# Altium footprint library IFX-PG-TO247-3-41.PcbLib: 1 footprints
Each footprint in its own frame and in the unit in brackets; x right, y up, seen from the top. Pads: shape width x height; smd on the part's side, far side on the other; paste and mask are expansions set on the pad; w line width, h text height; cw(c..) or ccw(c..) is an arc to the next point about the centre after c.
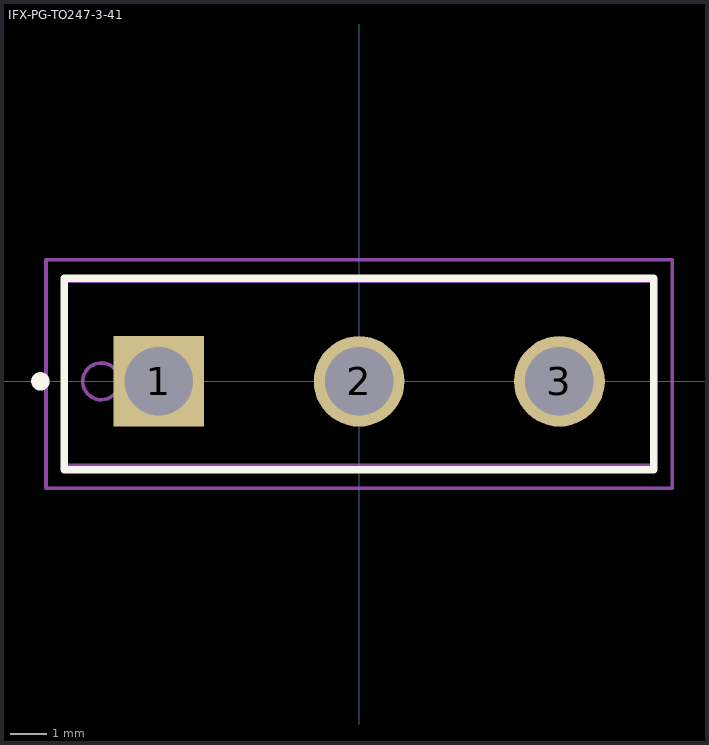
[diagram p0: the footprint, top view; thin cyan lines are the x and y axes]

## IFX-PG-TO247-3-41 [mm] "TO247-Diode; 3 pin, 5.44 mm pitch, 15.90 mm L X 5.00 mm W X 26.00 mm H body"
height 26
pads (3):
  rect 2.46x2.46 hole 1.86 paste+0 mask+0: 1(-5.44,0)
  round 2.46 hole 1.86 paste+0 mask+0: 2(0,0) 3(5.44,0)
Top Overlay:
  circle w0.25: c-8.65,0 r0.125
  lines w0.2: -8,-2.4 8,-2.4 8,2.8 -8,2.8 -8,-2.4
M3 (ASY_Text_Top):
  text ".DESIGNATOR" at 0,0 h1.2
M13 (CMP_Body_OTL_Top):
  circle w0.1: c-7,0 r0.5
  lines w0.1: -7.95,-2.282 -7.95,2.718 7.95,2.718 7.95,-2.282 -7.95,-2.282
M15 (CMP_Courtyard_Top):
  lines w0.1: -0.5,0 0.5,0 ; 0,-0.5 0,0.5 ; -8.5,-2.9 8.5,-2.9 8.5,3.3 -8.5,3.3 -8.5,-2.9
3D body "AIDW10S65C5.STEP": height 26, standoff -15.9, extent -7.95,-2.232 7.95,2.768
